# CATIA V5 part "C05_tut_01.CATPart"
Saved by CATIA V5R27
Part number: Part1
Bounding box of the stored display mesh (mm): x -20 to 20, y 0 to 95, z 0 to 40
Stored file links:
  E:\_Deepak\2017_Deepak\CATIA\Resources\Tutorial Files\Tutorials\c05_catia_v5_6r2016_tut\C05_tut_01.CATPart
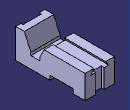
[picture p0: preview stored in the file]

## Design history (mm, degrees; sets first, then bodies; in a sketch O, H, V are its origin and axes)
Body1 (main body)
  Sketch1 on yz-plane, origin (0, 0, 0), H (0, 1, 0), V (0, 0, 1)
    point P1 (0, 0)
    line L1 (0, 0) -> (0, 40)
    line L2 (0, 40) -> (12, 40)
    point P3 (12, 40)
    line L3 (12, 40) -> (21, 20)
    line L4 (21, 20) -> (21, 16)
    line L5 (21, 16) -> (33, 16)
    line L6 (33, 16) -> (33, 20)
    point P7 (33, 20)
    line L7 (33, 20) -> (39, 32)
    point P8 (39, 32)
    line L8 (39, 32) -> (95, 32)
    line L9 (95, 32) -> (95, 0)
    point P10 (95, 0)
    line L10 (95, 0) -> (79, 0)
    line L11 (79, 0) -> (79, 6)
    line L12 (79, 6) -> (47, 6)
    line L13 (47, 6) -> (47, 0)
    point P14 (47, 0)
    line L14 (47, 0) -> (0, 0)
    reference intersected line E1 through (0, 0) direction (0, 1) from zx-plane
    length L1 = 40
    length L2 = 12
    distance P8 P7 V = 12
    distance L1 L9 = 95
    distance P8 P7 H = 6
    length L9 = 32
    length L12 = 32
    length L11 = 6
    length L4 = 4
    distance L5 L14 = 16
    distance L11 L9 = 16
    distance P3 P8 H = 27
    length L5 = 12
    coincidence: P1 H, P10 H, P14 H, L1 E1
    vertical: L1 V, L4 V, L6 V, L9 V, L11 V, L13 V
    horizontal: L2 H, L5 H, L8 H, L10 H, L12 H, L14 H
  Pad1: profile Sketch1, direction (1, 0, 0), length 20, mirrored extent
  Sketch2 on face of Pad1 from Sketch1.L9, origin (0, 95, 0), H (-1, 0, 0), V (0, 0, 1)
    point P1 (-8, 32)
    line L1 (-8, 32) -> (-12.0471, 26)
    point P2 (-12.0471, 26)
    line L2 (-12.0471, 26) -> (12.0471, 26)
    point P3 (12.0471, 26)
    line L3 (12.0471, 26) -> (8, 32)
    point P4 (8, 32)
    line L4 (8, 32) -> (-8, 32)
    reference projected line E1 (20, 32) -> (-20, 32) from edge [face of Pad1 from Sketch1.L8 | face of Pad1 from Sketch1.L9]
    length L4 = 16
    distance L2 H = 26
    angle L2 L3 = 56
    horizontal: L2 H, L4 H
    symmetry: P4 P1 V, P3 P2 V
    coincidence: L4 E1
  Pocket1: profile Sketch2, direction (0, -1, 0), through (limit type 6)
  Sketch3 on face of Pad1 from Sketch1.L9, origin (0, 95, 0), H (-1, 0, 0), V (0, 0, 1)
    line L1 (-6, 26) -> (6, 26)
    line L2 (6, 26) -> (6, 0)
    line L3 (6, 0) -> (-6, 0)
    line L4 (-6, 0) -> (-6, 26)
    reference projected line E1 (-12.0471, 26) -> (12.0471, 26) from edge [face of Pad1 from Sketch1.L9 | face of Pocket1 from Sketch2.L2]
    reference projected line E2 (20, 0) -> (-20, 0) from edge [face of Pad1 from Sketch1.L9 | face of Pad1 from Sketch1.L10]
    distance L4 L2 = 12
    distance V L2 = 6
    horizontal: L1 H, L3 H
    vertical: L2 V, L4 V
    coincidence: L1 E1, L3 E2
  Pocket2: profile Sketch3, direction (0, -1, 0), length 4
  Sketch4 on face of Pad1 from Sketch1.L2, origin (0, 0, 40), H (1, 0, 0), V (0, 1, 0)
    line L1 (-12.5, 0) -> (12.5, 0)
    line L2 (12.5, 0) -> (12.5, 3)
    line L3 (12.5, 3) -> (-12.5, 3)
    line L4 (-12.5, 3) -> (-12.5, 0)
    reference projected line E1 (-20, 0) -> (20, 0) from edge [face of Pad1 from Sketch1.L1 | face of Pad1 from Sketch1.L2]
    reference projected line E2 (-20, 0) -> (20, 0) from edge [face of Pad1 from Sketch1.L1 | face of Pad1 from Sketch1.L2]
    length L1 = 25
    distance E1 L3 = 3
    horizontal: L1 H, L3 H
    vertical: L2 V, L4 V
    symmetry: L4 L2 V
    coincidence: L1 E2
  Pocket3: profile Sketch4, direction (0, 0, -1), through (limit type 3)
